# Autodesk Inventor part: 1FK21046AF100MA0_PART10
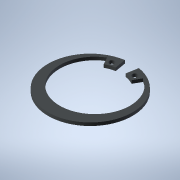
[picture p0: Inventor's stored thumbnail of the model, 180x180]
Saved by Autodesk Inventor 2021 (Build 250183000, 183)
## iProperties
Created: 2025-04
Part Number: 1FK21046AF100MA0_PART10
Material: Generic
Catalog Web Link: www.3dfindit.com
Description: -Servo synchronous motor
Document SubType Name: Modeling
Designer: psAdmin
Mass: 0.642463 g
Surface Area: 12.3927 cm^2
Volume: 0.642463 cm^3
Density: 1 g/cm^3
Appearance: PSOLRGB-212-217-219
Category: PARTsolutions
Title: 1FK21046AF100MA0_PART10
Author: Cadenas PARTsolutions
Comments: Servo synchronous motor
Sending System: PARTsolutions
Preprocessor: ST-DEVELOPER v19.3
PSOL_IDENT_0: {$CADENAS_DATA/23d-libs/siemens_ag/_cat_/4f/2b/1fk21046af100ma0.prj},216 {VTYP=3D},{NB=1FK21046AF100
PSOL_IDENT_1: MA0_PART10},{LINA=1FK21046AF100MA0_PART10},{NN=1FK21046AF100MA0_PART10},{NOPRJ=TRUE},{DATE=19.08.202
PSOL_IDENT_2: 5 14:00:37},{GEOMDATE=30.07.2025 02:01:06},{VERSION=},{LINEID=10},{WBVAR=},{WBNUMERIC=}  {NB=1FK2104
PSOL_IDENT_3: 6AF100MA0_PART10},{LINA=1FK21046AF100MA0_PART10},{KT=DUMMY},{PREVIEW=../../../_pool_/cb/72/p_d211_xx
PSOL_IDENT_4: _00434j.png},{DESCSHORT=SIMOTICS S-1FK2 HD, SINAMICS S210 3AC 400V-480V, 3.2 Nm, 3000 rpm},{DESCLONG=
PSOL_IDENT_5: SIMOTICS S-1FK2 HD servo motor M0=3.2 Nm; PN = 1 kW at nN=3000 rpm (380-480 V); PN = 0.5 kW at nN=15
PSOL_IDENT_6: 00 rpm (200-240 V); with holding brake; degree of protection IP64; cylindrical shaft D19x40mm; absol
PSOL_IDENT_7: ute encoder 22-bit + 12-bit multiturn (encoder AM22DQC); with OCC interface; plug size M17, rotatabl
PSOL_IDENT_8: e; SIMOTICS S-1FK2 servomotorfor a wide range of uses in industrial environments. SIMOTICS S‑1FK2 se
PSOL_IDENT_9: rvomotors are compact synchronous motors with a high dynamic performance that set themselves apart a
PSOL_IDENT_10: s a result of their high power density, degree of protection and overload capability. The motors are
PSOL_IDENT_11: available in two variants: as High Dynamic variant (highest dynamic performance as a result of the
PSOL_IDENT_12: low intrinsic moment of inertia for applications demanding a high dynamic performance with low moved
PSOL_IDENT_13: masses) - and as Compact variant (precise and stable closed-loop control for medium up to large mov
PSOL_IDENT_14: ed masses as a result of a medium intrinsic moment of inertia). SIMOTICSS‑1FK2 servomotors fully exp
PSOL_IDENT_15: loit their strengths in a system with the SINAMICSS210 frequency converter and simple connection usi
PSOL_IDENT_16: ng the one cable connection (OCC). Advantages include the short control and positioning times, fast
PSOL_IDENT_17: and precise correction of disturbing quantities as well as stable control with a high dynamic perfor
PSOL_IDENT_18: mance. The servo motors can be configured to address a wide range of requirements. For example with
PSOL_IDENT_19: and without holding brake, IP64 or IP65 degree of protection, singleturn or multiturn absolute encod
PSOL_IDENT_20: ers - to name just a few. Further, the servomotors are available in different shaft heights extendin
PSOL_IDENT_21: g from 20 to 100. A shaft sealing ring is available to achieve an IP65 degree of protection and for
PSOL_IDENT_22: subsequent mounting at the motor or as spare part. SIMOTICS - the optimum motor for each and every m
PSOL_IDENT_23: otion control application.},{INTNO=195125049673},{SUPPLIERALTNO=1FK2104-6AF10-0MA0},{MANUID=1FK21046
PSOL_IDENT_24: AF100MA0},{MANUNAME=Siemens},{MANUTYPEDESC=Synchronous motor 1FK2-HD 3.2 NM},{AAU732=SIMOTICS},{AAO0
PSOL_IDENT_25: 57=S-1FK2},{AAU734=SIMOTICS S-1FK2 HD servo motor M0=3.2 Nm; PN = 1 kW at nN=3000 rpm (380-480 V); P
PSOL_IDENT_26: N = 0.5 kW at nN=1500 rpm (200-240 V); with holding brake; degree of protection IP64; cylindrical sh
PSOL_IDENT_27: aft D19x40mm; absolute encoder 22-bit + 12-bit multiturn (encoder AM22DQC); with OCC interface; plug
PSOL_IDENT_28: size M17, rotatable;},{AAW338=Synchronous motor 1FK2-HD 3.2 NM},{AAO742=SIMOTICS},{AAO663=404294869
PSOL_IDENT_29: 4534},{NOCUPEROU=1},{PRICEQUANTITY=1},{QUANTITYMIN=1},{QUANTITYINT=1},{CTN=85015220},{COO=DE},{AAO67
PSOL_IDENT_30: 6=1FK2104-6AF10-0MA0},{AAO677=Siemens AG},{ORDERUNIT=C62},{CONTENTUNIT=C62}
NB: 1FK21046AF100MA0_PART10
NT: Servo synchronous motor
NBSYN: $MANUID._PART10
LINA: 1FK21046AF100MA0_PART10
CATALOG: SIEMENS
PREVIEW: ../../../_pool_/cb/72/p_d211_xx_00434j.png
DESCSHORT: SIMOTICS S-1FK2 HD, SINAMICS S210 3AC 400V-480V, 3.2 Nm, 3000 rpm
DESCLONG: SIMOTICS S-1FK2 HD servo motor M0=3.2 Nm; PN = 1 kW at nN=3000 rpm (380-480 V); PN = 0.5 kW at nN=1500 rpm (200-240 V); with holding brake; degree of protection
INTNO: 195125049673
SUPPLIERALTNO: 1FK2104-6AF10-0MA0
MANUID: 1FK21046AF100MA0
MANUNAME: Siemens
MANUTYPEDESC: Synchronous motor 1FK2-HD 3.2 NM
AAU732: SIMOTICS
AAO057: S-1FK2
AAU734: SIMOTICS S-1FK2 HD servo motor M0=3.2 Nm; PN = 1 kW at nN=3000 rpm (380-480 V); PN = 0.5 kW at nN=1500 rpm (200-240 V); with holding brake; degree of protection
AAW338: Synchronous motor 1FK2-HD 3.2 NM
AAO742: SIMOTICS
AAO663: 4042948694534.0
NOCUPEROU: 1
PRICEQUANTITY: 1
QUANTITYMIN: 1
QUANTITYINT: 1
CTN: 85015220
COO: DE
ARTICLENO: 1FK21046AF100MA0_PART10
BOMINFO: 1FK21046AF100MA0_PART10
CREATOR: CADENAS GmbH
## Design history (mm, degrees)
feature "2025_04_17_14_59_39_0177"
body "Solid1"
